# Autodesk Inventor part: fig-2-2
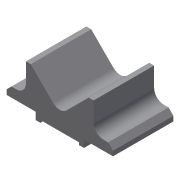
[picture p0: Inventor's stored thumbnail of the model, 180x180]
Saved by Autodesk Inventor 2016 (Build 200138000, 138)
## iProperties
Shininess: 64.0
Length Units: 11269
Angle Units: 11279
Time Units: 11290
Mass Units: 11283
Length Display Precision: 3
Angle Display Precision: 2
Compacted: True
Part Number: fig-2-2
Document SubType Name: Modeling
Created: 2002-11
Designer: deepak
Density: 1 g/cm^3
Material: Generic
Appearance: Default
Density: 0.0
Volumn: 0.0
Area: 0.0
PropertySet Name: Model Information
Control State: 0
Master: False
Checked Out: False
Author: CADCIM
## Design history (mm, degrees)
sketch "Sketch1"
  geometry: L1 (0, 0)-(-3, 3); L2 (-3, 3)-(-3.5, 3); L3 (-3.5, 3)-(-3.5, 0); L4 (-3.5, 0)-(-5.5, 0); L5 (-5.5, 0)-(-5.5, -1); L6 (-5.5, -1)-(-2.5, -1); L7 (-2.5, -1)-(-2.5, -1.75); L8 (-2.5, -1.75)-(-2, -1.75); L9 (-2, -1.75)-(-2, -1.5); L10 (-2, -1.5)-(2, -1.5); L11 (2, -1.5)-(2, -1.75); L12 (2, -1.75)-(2.5, -1.75); L13 (2.5, -1.75)-(2.5, -1); L14 (2.5, -1)-(5.5, -1); L15 (5.5, -1)-(5.5, 0); L16 (5.5, 0)-(3.5, 0); L17 (3.5, 0)-(3.5, 3); L18 (3.5, 3)-(3, 3); L19 (3, 3)-(0, 0)
  constraints: 38 end point, 17 perpendicular, 1 horizontal
extrude "Extrusion1" new body sketch "Sketch1" distance "d0" = 6.25; taper "d1" = 0 deg
fillet "Fillet1" dims "d2" = 1
chamfer "Chamfer1" distance "d3" = 0.5; stored, may be unused: second distance "d4" = 2, angle "d5" = 45 deg
body "Solid1"
